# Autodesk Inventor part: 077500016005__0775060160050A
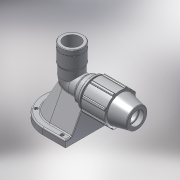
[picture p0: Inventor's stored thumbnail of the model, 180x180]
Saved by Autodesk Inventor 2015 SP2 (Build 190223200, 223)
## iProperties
Created: 2017-02
Part Number: 077500016005__0775060160050A
Material: PVC-Piping
Description: PLASSON WALL PLATE ELBOW 16-1/2"
Document SubType Name: Modeling
Designer: KIM
Mass: 92.6774 g
Surface Area: 199.44 cm^2
Volume: 66.1981 cm^3
Density: 1.4 g/cm^3
Appearance: Smooth - White
Author: KIM
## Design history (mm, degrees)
derived "07750.ipt"
feature "Solid1::07750.ipt"
feature "Solid2::07750.ipt"
tag "TaggingFeature1"
body "Solid1"
other parameters: "d2" = 16, "d4" = 6.33333, "d5" = 19, "d7" = 39, "d9" = 10.85714, "d11" = 2.53333, "d13" = 120 deg, "d14" = 24, "d15" = 12 deg, "d16" = 33.93, "d18" = 0.8, "d19" = 35 deg, "d20" = 17.5 deg, "d21" = 36.27, "d23" = 0, "d25" = 360 deg, "d27" = 0.78, "d33" = 0.32, "d42" = 28.12, "d43" = 1.17, "d46" = 0.48, "d51" = 76, "d68" = 2.53333, "d76" = 18.631, "d77" = 20.9, "d79" = 7.4524, "d80" = 0.55893, "d83" = 0, "d84" = 0, "d91" = 29.25, "d94" = 18.631, "d95" = 13.0417, "d96" = 6.33333, "d97" = 50 deg, "d98" = 16.7679, "d99" = 0.5, "d100" = 0.5, "d101" = 6.33333, "d112" = 19, "d113" = 26.0834, "d114" = 24.2203, "d115" = -38, "d116" = 7.6, "d118" = 7.6, "d119" = 0, "d120" = 0, "d121" = 90 deg, "d122" = 0, "d123" = 90 deg, "d124" = 1.52, "d126" = 7.6, "d127" = 0, "d128" = 1.52, "d129" = 1.52, "d130" = 6.08, "d131" = 0, "d132" = 1.52, "d133" = 0.76, "d134" = 4, "d135" = 7.6, "d136" = 4, "d137" = 3.8, "d138" = 49.4, "d139" = 15.2, "d141" = 0, "d_" = 16, "E_" = 39, "A_" = 76, "l_1" = 19, "Rp_" = 18.631, "A_2" = 38
